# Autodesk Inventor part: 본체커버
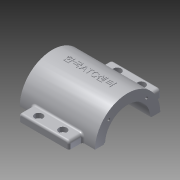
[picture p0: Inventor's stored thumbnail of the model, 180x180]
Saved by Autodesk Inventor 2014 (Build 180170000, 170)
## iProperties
Created: 2015-12
Part Number: 본체커버
Material: 알루미늄 6061
Document SubType Name: Modeling
Designer: mduedu
Density: 2.71 g/cm^3
Mass: 199.348 g
Surface Area: 200.806 cm^2
Volume: 73.5601 cm^3
Appearance: 알루미늄 - 평지
Author: mduedu
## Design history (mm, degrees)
sketch "스케치1"
  geometry: L1 (45, 40)-(-45, 40); L2 (-45, 40)-(-45, -40); L3 (-45, -40)-(45, -40); L4 (45, -40)-(45, 40); L5 (45, 40)-(-45, -40); L6 (-45, 40)-(45, -40); 1 further point
  constraints: 12 end point, 2 midpoint, 2 parallel, 1 horizontal, 1 perpendicular
  dimensions: "d0" = 90 distance of L2.end L3.end; "d2" = 80 distance of L1.end L2.end
extrude "돌출1" new body sketch "스케치1" distance "d3" = 10; taper "d4" = 0 deg
sketch "스케치2"
  geometry: L1 (0, 40)-(0, -40) reference; C1 r 32.5 at (80, 0); 1 further point
  constraints: 1 centre point
  dimensions: "d5" = 65 diameter of C1; "d6" = 80 distance from line of C1.centre L1
extrude "돌출2" join sketch "스케치2" stored distance "d7" = 75; taper "d8" = 0 deg
sketch "스케치3"
  geometry: L1 (-27.5, -20)-(27.5, -20); L2 (27.5, -20)-(27.5, 20); L3 (27.5, 20)-(-27.5, 20); L4 (-27.5, 20)-(-27.5, -20); L5 (-27.5, -20)-(27.5, 20); L6 (27.5, -20)-(-27.5, 20); 1 further point
  constraints: 12 end point, 2 midpoint, 2 parallel, 1 horizontal, 1 perpendicular
  dimensions: "d9" = 55 distance of L2.end L3.end; "d11" = 40 distance of L1.end L2.end
extrude "돌출3" new body sketch "스케치3" stored distance "d12" = 75; taper "d13" = 0 deg
fillet "모깎기1"
fillet "모깎기2"
feature "결합1"
  node "솔리드2"
fillet "모깎기3" dims "d14" = 10
sketch "스케치4"
  geometry: L1 (-37.5, 47.5)-(37.5, 47.5) reference; L2 (35, 10)-(45, 10) reference; L3 (32.5, 47.5)-(40, 10); L4 (37.5, 47.5)-(37.5, 112.5) reference; L5 (45, 10)-(45, 0) reference; 1 further point
  constraints: 2 end point, 1 midpoint, 1 point on line
  dimensions: "d15" = 5 distance from line of L3.start L4; "d16" = 5 distance from line of L3.end L5
sketch "스케치5"
  geometry: L1 (10, 40)-(10, 30) reference; L2 (10, 35)-(56.569, 22.522); L3 (0, 40)-(10, 40) reference; 2 further points
  constraints: 2 end point, 1 midpoint, 2 other
  dimensions: "d17" = 5 distance from line of L2.start L3; "d18" = 15 deg angle of L2 L3
feature "리브1" dims "d19" = 1, "d20" = 6, "d21" = 0, "d22" = 0, "d23" = 1, "d24" = 1
feature "리브2" dims "d25" = 1, "d26" = 6, "d27" = 0, "d28" = 0, "d29" = 1, "d30" = 1
fillet "모깎기4" dims "d31" = 2
fillet "모깎기5" dims "d32" = 2
fillet "모깎기6" dims "d33" = 2
sketch "스케치6"
  geometry: A1 r 10 centre (-35, 30) between (-35, 40) and (-45, 30) reference; A2 r 10 centre (35, 30) between (45, 30) and (35, 40) reference; A3 r 10 centre (35, -30) between (35, -40) and (45, -30) reference; A4 r 10 centre (-35, -30) between (-45, -30) and (-35, -40) reference; 5 further points
  constraints: 4 coincident
hole "구멍1" sketch "스케치6" at (-35, 30), (35, 30), (35, -30), (-35, -30) diameter "d34" = 7; stored, may be unused: countersink angle "d38" = 90 deg, drill point angle "d40" = 118 deg; dims "d35" = 6, "d36" = 12, "d37" = 3, "d39" = 8
fillet "모깎기7" dims "d41" = 2
hole "구멍2" diameter "d44" = 45; stored, may be unused: countersink angle "d48" = 90 deg, drill point angle "d50" = 118 deg; dims "d42" = 10, "d43" = 10, "d45" = 6, "d46" = 4, "d47" = 2, "d49" = 8
sketch "스케치7" dims "d52" = 26.5
  geometry: L1 (0, 0)-(32.5, 0); L2 (0, 0)-(22.981, 22.981); A1 r 32.5 centre (0, 0) between (32.5, 0) and (22.981, 22.981) reference; 3 further points
  constraints: 4 end point, 2 point on circle, 1 coincident, 1 horizontal, 1 point on line, 3 other
  dimensions: "d51" = 45 deg angle of L2 L1
hole "구멍3" sketch "스케치7" at (18.738, 18.738) diameter "d54" = 2.459; stored, may be unused: countersink angle "d58" = 90 deg, drill point angle "d60" = 118 deg; dims "d55" = 8, "d56" = 4, "d57" = 2, "d59" = 10
sketch "스케치8"
  geometry: L1 (72.5, 31.623)-(72.5, 46); L2 (72.5, 46)-(87.5, 46); L3 (87.5, 46)-(87.5, 31.623); A1 r 32.5 centre (80, 0) between (87.5, 31.623) and (72.5, 31.623) reference; 2 further points
  constraints: 6 end point, 2 point on circle, 1 midpoint, 1 parallel, 1 vertical, 1 vertical alignment
  dimensions: "d64" = 15 distance of L1.end L2.end; "d66" = 46 distance from line of L2 A1.centre
extrude "돌출4" join sketch "스케치8" stored distance "d67" = 50; taper "d68" = 0 deg
fillet "모깎기8" dims "d69" = 3
fillet "모깎기9" dims "d70" = 2
sketch "스케치13"
  geometry: L1 (-46, 80)-(106, 80); L2 (106, 80)-(106, -30); L3 (106, -30)-(-46, -30); L4 (-46, -30)-(-46, 80); L5 (0, 0)-(60, 0) reference; L6 (76, 75.5)-(76, 84.5) reference; C1 r 32.5 at (30, 80) reference; 1 further point
  constraints: 8 end point, 2 parallel, 1 coincident, 1 horizontal, 1 midpoint, 1 perpendicular
  dimensions: "d99" = 30 distance between parallel lines of L3 L5; "d100" = 30 distance between parallel lines of L2 L6
extrude "돌출8" cut sketch "스케치13" stored distance "d97" = 10; taper "d98" = 0 deg
node "작업 평면2"
sketch "스케치14"
  geometry: 2 further points
  constraints: 1 coincident, 1 other
feature "엠보싱1" sketch "스케치14" dims "d28" = 0, "d102" = 0.5, "d103" = 0
feature "립1" dims "d104" = 1, "d105" = 1.1, "d106" = 0, "d107" = 0, "d108" = 3 deg, "d109" = 0
sketch "스케치15"
  geometry: L1 (-3, -1.039)-(-3, -10.834) reference; L2 (47, -10.834)-(47, -1.039) reference; L3 (-3, -5.936)-(47, -5.936); L4 (-15.5, 65.666)-(-15.5, 0.666) reference; L5 (59.5, 0.666)-(59.5, 65.666) reference; L6 (-15.5, 33.166)-(59.5, 33.166); 5 further points
  constraints: 4 end point, 4 midpoint, 2 point on line, 2 symmetric about line
  dimensions: "d110" = 13 distance from line of point (10, -5.936) L1; "d111" = 13 distance from line of point (34, -5.936) L2
sketch "스케치16"
  geometry: 4 further points
hole "구멍5" sketch "스케치16" at (34, -5.936), (10, 72.269), (34, 72.269), (10, -5.936) diameter "d112" = 4.5; stored, may be unused: countersink angle "d116" = 90 deg, drill point angle "d118" = 0 deg; dims "d113" = 6, "d114" = 8, "d115" = 4.6, "d117" = 8
node "솔리드1"
mirror "대칭1"
mirror "대칭2"
pattern_circular "원형 패턴1" dims angle "d62" = 360 deg
mirror "대칭3"
mirror "대칭4"
